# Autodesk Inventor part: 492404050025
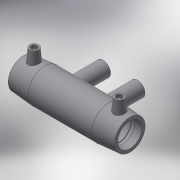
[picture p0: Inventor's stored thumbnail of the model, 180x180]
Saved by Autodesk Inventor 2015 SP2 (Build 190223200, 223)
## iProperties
Created: 2017-06
Part Number: 492404050025
Material: Generic
Description: PLASSON REDUCING TEE WITH TWO OUTLETS 50X25X25X50
Document SubType Name: Modeling
Designer: KIM
Mass: 57.3761 g
Surface Area: 241.06 cm^2
Volume: 57.3761 cm^3
Density: 1 g/cm^3
Appearance: Default
Author: KIM
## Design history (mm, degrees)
derived "492404.ipt"
feature "Solid1::492404.ipt"
tag "TaggingFeature1"
body "Solid1"
other parameters: "d0" = 195, "d2" = 68, "d3" = 49, "d4" = 39, "d5" = 61.2, "d6" = 47.5, "d8" = 168 deg, "d10" = 19.6, "d11" = 6.53333, "d23" = 68, "d29" = 51, "d30" = 15, "d31" = 78, "d34" = 5 deg, "d41" = 4, "d42" = 14, "d43" = 0, "d48" = -79, "d49" = 25, "d51" = 0, "d62" = 79, "d74" = -79, "d84" = 25, "d85" = 65, "d86" = 32.5, "d90" = 0, "d91" = 3, "d92" = 0, "L_" = 195, "L_1" = 49, "D_" = 68, "A_" = 51, "d_2" = 12, "H_" = 79, "L_2" = 65, "d_1" = 25
